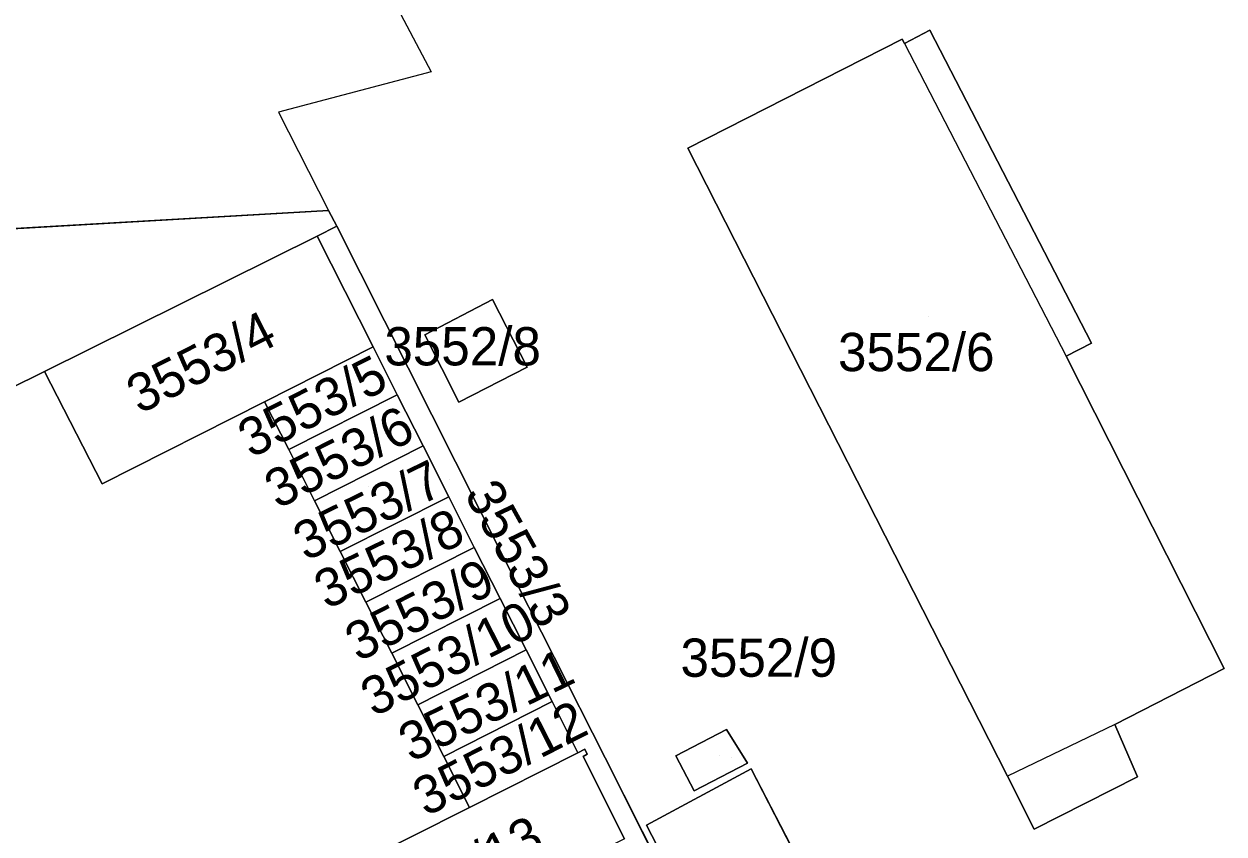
# Model space of a CAD drawing. Extents: x -262657 to -261595, y -1238015 to -1237156.
# Drawn here: x -262494.6 to -262431.9, y -1237435.4 to -1237393.1 of the extents above; entities that cross this region are included whole.
import ezdxf

# ---------------------------------------------------------------- set-up
doc = ezdxf.new("R2010")
doc.units = 0
for name, color, linetype in [('body_kn', 7, 'Continuous'), ('kladpar_druhypozemkov', 7, 'Continuous'), ('kladpar_hranice', 7, 'Continuous'), ('kladpar_parcelnecisla', 7, 'Continuous'), ('kladpar_plochy', 7, 'Continuous'), ('kladpar_sipky', 7, 'Continuous'), ('zappar_hrandruhpozemk', 7, 'Continuous')]:
    doc.layers.add(name, color=color, linetype=linetype)

msp = doc.modelspace()

# ---------------------------------------------------------------- linework, layer by layer
at = {"layer": 'body_kn'}
for p, q in [((-262448.76, -1237393.9), (-262448.76, -1237393.9)), ((-262447.31, -1237393.44), (-262447.31, -1237393.44)), ((-262448.64, -1237394.13), (-262448.64, -1237394.13)), ((-262448.64, -1237394.13), (-262448.64, -1237394.13)), ((-262473.37, -1237395.61), (-262473.37, -1237395.61)), ((-262481.34, -1237397.71), (-262481.34, -1237397.71)), ((-262459.95, -1237399.59), (-262459.95, -1237399.59)), ((-262459.95, -1237399.59), (-262459.95, -1237399.59)), ((-262478.73, -1237402.85), (-262478.73, -1237402.85)), ((-262478.29, -1237403.67), (-262478.29, -1237403.67)), ((-262478.29, -1237403.67), (-262478.29, -1237403.67)), ((-262479.33, -1237404.19), (-262479.33, -1237404.19)), ((-262479.33, -1237404.19), (-262479.33, -1237404.19)), ((-262470.16, -1237407.5), (-262470.16, -1237407.5)), ((-262470.16, -1237407.5), (-262470.16, -1237407.5)), ((-262473.69, -1237409.35), (-262473.69, -1237409.35)), ((-262476.4, -1237409.98), (-262476.4, -1237409.98)), ((-262476.4, -1237409.98), (-262476.4, -1237409.98)), ((-262438.86, -1237409.78), (-262438.86, -1237409.78)), ((-262440.19, -1237410.47), (-262440.19, -1237410.47)), ((-262493.57, -1237411.26), (-262493.57, -1237411.26)), ((-262468.36, -1237411.05), (-262468.36, -1237411.05)), ((-262475.14, -1237412.48), (-262475.14, -1237412.48)), ((-262475.14, -1237412.48), (-262475.14, -1237412.48)), ((-262482.07, -1237412.85), (-262482.07, -1237412.85)), ((-262471.92, -1237412.87), (-262471.92, -1237412.87)), ((-262473.79, -1237415.15), (-262473.79, -1237415.15)), ((-262473.79, -1237415.15), (-262473.79, -1237415.15)), ((-262480.81, -1237415.34), (-262480.81, -1237415.34)), ((-262490.55, -1237417.14), (-262490.55, -1237417.14)), ((-262479.46, -1237418.02), (-262479.46, -1237418.02)), ((-262472.45, -1237417.81), (-262472.45, -1237417.81)), ((-262472.45, -1237417.81), (-262472.45, -1237417.81)), ((-262478.12, -1237420.68), (-262478.12, -1237420.68)), ((-262471.12, -1237420.46), (-262471.12, -1237420.46)), ((-262471.12, -1237420.46), (-262471.12, -1237420.46)), ((-262469.6, -1237420.93), (-262469.6, -1237420.93)), ((-262476.78, -1237423.32), (-262476.78, -1237423.32)), ((-262469.77, -1237423.13), (-262469.77, -1237423.13)), ((-262469.77, -1237423.13), (-262469.77, -1237423.13)), ((-262468.41, -1237425.82), (-262468.41, -1237425.82)), ((-262468.41, -1237425.82), (-262468.41, -1237425.82)), ((-262475.43, -1237425.99), (-262475.43, -1237425.99)), ((-262431.94, -1237426.78), (-262431.94, -1237426.78)), ((-262474.07, -1237428.68), (-262474.07, -1237428.68)), ((-262467.05, -1237428.52), (-262467.05, -1237428.52)), ((-262467.05, -1237428.52), (-262467.05, -1237428.52)), ((-262457.94, -1237429.98), (-262457.94, -1237429.98)), ((-262437.65, -1237429.72), (-262437.65, -1237429.72)), ((-262437.65, -1237429.72), (-262437.65, -1237429.72)), ((-262472.71, -1237431.38), (-262472.71, -1237431.38)), ((-262465.7, -1237431.19), (-262465.7, -1237431.19)), ((-262465.7, -1237431.19), (-262465.7, -1237431.19)), ((-262465.43, -1237431.39), (-262465.43, -1237431.39)), ((-262465.34, -1237431.01), (-262465.34, -1237431.01)), ((-262465.21, -1237431.27), (-262465.21, -1237431.27)), ((-262464.28, -1237431.46), (-262464.28, -1237431.46)), ((-262460.58, -1237431.35), (-262460.58, -1237431.35)), ((-262460.58, -1237431.35), (-262460.58, -1237431.35)), ((-262456.84, -1237431.73), (-262456.84, -1237431.73)), ((-262456.65, -1237432.03), (-262456.65, -1237432.03)), ((-262443.26, -1237432.42), (-262443.26, -1237432.42)), ((-262436.46, -1237432.44), (-262436.46, -1237432.44)), ((-262459.63, -1237433.18), (-262459.63, -1237433.18)), ((-262471.37, -1237434.05), (-262471.37, -1237434.05)), ((-262462.11, -1237434.98), (-262462.11, -1237434.98)), ((-262462.11, -1237434.98), (-262462.11, -1237434.98)), ((-262441.86, -1237435.18), (-262441.86, -1237435.18))]:
    msp.add_line(p, q, dxfattribs=at)
at = {"layer": 'kladpar_druhypozemkov'}
for p, q in [((-262447.37, -1237408.4), (-262447.37, -1237408.4)), ((-262484.67, -1237409.31), (-262484.67, -1237409.31)), ((-262470.61, -1237409.19), (-262470.61, -1237409.19)), ((-262479.21, -1237411.98), (-262479.21, -1237411.98)), ((-262477.97, -1237414.73), (-262477.97, -1237414.73)), ((-262472.42, -1237416.89), (-262472.42, -1237416.89)), ((-262476.65, -1237417.29), (-262476.65, -1237417.29)), ((-262475.37, -1237420.02), (-262475.37, -1237420.02)), ((-262474.18, -1237422.69), (-262474.18, -1237422.69)), ((-262472.66, -1237425.55), (-262472.66, -1237425.55)), ((-262471.32, -1237427.85), (-262471.32, -1237427.85)), ((-262469.89, -1237430.69), (-262469.89, -1237430.69)), ((-262458.31, -1237431.31), (-262458.31, -1237431.31))]:
    msp.add_line(p, q, dxfattribs=at)
at = {"layer": 'kladpar_hranice'}
for points in [[(-262437.9, -1237483.33), (-262449.72, -1237460.31), (-262464.28, -1237431.46), (-262469.6, -1237420.93), (-262478.29, -1237403.67), (-262478.73, -1237402.85), (-262506.09, -1237404.44), (-262514.95, -1237386.75), (-262519.84, -1237377.16), (-262513.51, -1237373.66), (-262507.3, -1237370.26), (-262500.71, -1237366.65), (-262500.15, -1237367.7), (-262490.13, -1237386.72), (-262486.03, -1237384.56), (-262484.61, -1237387.26), (-262481.8, -1237385.78), (-262483.22, -1237383.08), (-262479.4, -1237381.2)], [(-262478.29, -1237403.67), (-262479.33, -1237404.19), (-262493.57, -1237411.26), (-262501.01, -1237414.95), (-262518.77, -1237390.55), (-262514.95, -1237386.75), (-262506.09, -1237404.44), (-262478.73, -1237402.85), (-262478.29, -1237403.67)], [(-262459.95, -1237399.59), (-262448.76, -1237393.9), (-262448.64, -1237394.13), (-262447.31, -1237393.44), (-262438.86, -1237409.78), (-262440.19, -1237410.47), (-262431.94, -1237426.78), (-262437.65, -1237429.72), (-262436.46, -1237432.44), (-262441.86, -1237435.18), (-262443.26, -1237432.42), (-262459.95, -1237399.59)], [(-262448.76, -1237393.9), (-262459.95, -1237399.59), (-262443.26, -1237432.42), (-262441.86, -1237435.18), (-262436.46, -1237432.44), (-262437.65, -1237429.72), (-262431.94, -1237426.78), (-262440.19, -1237410.47), (-262438.86, -1237409.78), (-262447.31, -1237393.44), (-262448.64, -1237394.13), (-262448.76, -1237393.9)], [(-262463.26, -1237435.69), (-262465.43, -1237431.39), (-262465.21, -1237431.27), (-262465.34, -1237431.01), (-262465.7, -1237431.19), (-262467.05, -1237428.52), (-262468.41, -1237425.82), (-262469.77, -1237423.13), (-262471.12, -1237420.46), (-262472.45, -1237417.81), (-262473.79, -1237415.15), (-262475.14, -1237412.48), (-262476.4, -1237409.98), (-262479.33, -1237404.19), (-262478.29, -1237403.67)], [(-262478.29, -1237403.67), (-262469.6, -1237420.93), (-262464.28, -1237431.46), (-262449.72, -1237460.31)], [(-262479.33, -1237404.19), (-262476.4, -1237409.98), (-262482.07, -1237412.85), (-262490.55, -1237417.14), (-262493.57, -1237411.26), (-262479.33, -1237404.19)], [(-262470.16, -1237407.5), (-262468.36, -1237411.05), (-262471.92, -1237412.87), (-262473.69, -1237409.35), (-262470.16, -1237407.5)], [(-262468.36, -1237411.05), (-262470.16, -1237407.5), (-262473.69, -1237409.35), (-262471.92, -1237412.87), (-262468.36, -1237411.05)], [(-262476.4, -1237409.98), (-262475.14, -1237412.48), (-262480.81, -1237415.34), (-262482.07, -1237412.85), (-262476.4, -1237409.98)], [(-262501.01, -1237414.95), (-262493.57, -1237411.26), (-262490.55, -1237417.14), (-262482.07, -1237412.85), (-262480.81, -1237415.34), (-262479.46, -1237418.02), (-262478.12, -1237420.68), (-262476.78, -1237423.32), (-262475.43, -1237425.99), (-262474.07, -1237428.68), (-262472.71, -1237431.38), (-262471.37, -1237434.05), (-262480.58, -1237438.69), (-262480.44, -1237438.97), (-262480.06, -1237438.78), (-262477.9, -1237443.08), (-262475.74, -1237447.37), (-262473.58, -1237451.67), (-262471.42, -1237455.97), (-262469.26, -1237460.27), (-262467.1, -1237464.57), (-262467.48, -1237464.76), (-262467.34, -1237465.04), (-262464.28, -1237463.5)], [(-262475.14, -1237412.48), (-262473.79, -1237415.15), (-262479.46, -1237418.02), (-262480.81, -1237415.34), (-262475.14, -1237412.48)], [(-262473.79, -1237415.15), (-262472.45, -1237417.81), (-262478.12, -1237420.68), (-262479.46, -1237418.02), (-262473.79, -1237415.15)], [(-262472.45, -1237417.81), (-262471.12, -1237420.46), (-262476.78, -1237423.32), (-262478.12, -1237420.68), (-262472.45, -1237417.81)], [(-262471.12, -1237420.46), (-262469.77, -1237423.13), (-262475.43, -1237425.99), (-262476.78, -1237423.32), (-262471.12, -1237420.46)], [(-262469.77, -1237423.13), (-262468.41, -1237425.82), (-262474.07, -1237428.68), (-262475.43, -1237425.99), (-262469.77, -1237423.13)], [(-262468.41, -1237425.82), (-262467.05, -1237428.52), (-262472.71, -1237431.38), (-262474.07, -1237428.68), (-262468.41, -1237425.82)], [(-262467.05, -1237428.52), (-262465.7, -1237431.19), (-262471.37, -1237434.05), (-262472.71, -1237431.38), (-262467.05, -1237428.52)], [(-262460.58, -1237431.35), (-262457.94, -1237429.98), (-262456.84, -1237431.73), (-262459.63, -1237433.18), (-262460.58, -1237431.35)], [(-262457.94, -1237429.98), (-262460.58, -1237431.35), (-262459.63, -1237433.18), (-262456.84, -1237431.73), (-262457.94, -1237429.98)], [(-262465.7, -1237431.19), (-262465.34, -1237431.01), (-262465.21, -1237431.27), (-262465.43, -1237431.39), (-262463.26, -1237435.69), (-262477.9, -1237443.08), (-262480.06, -1237438.78), (-262480.44, -1237438.97), (-262480.58, -1237438.69), (-262471.37, -1237434.05), (-262465.7, -1237431.19)], [(-262462.11, -1237434.98), (-262456.65, -1237432.03), (-262433.8, -1237476.18), (-262439.24, -1237479.29), (-262462.11, -1237434.98)], [(-262456.65, -1237432.03), (-262462.11, -1237434.98), (-262439.24, -1237479.29), (-262433.8, -1237476.18), (-262456.65, -1237432.03)]]:
    msp.add_lwpolyline(points, dxfattribs=at)
at = {"layer": 'kladpar_plochy'}
for p, q in [((-262448.76, -1237393.9), (-262459.95, -1237399.59)), ((-262448.64, -1237394.13), (-262448.76, -1237393.9)), ((-262447.31, -1237393.44), (-262448.64, -1237394.13)), ((-262438.86, -1237409.78), (-262447.31, -1237393.44)), ((-262459.95, -1237399.59), (-262443.26, -1237432.42)), ((-262478.73, -1237402.85), (-262506.09, -1237404.44)), ((-262478.29, -1237403.67), (-262478.73, -1237402.85)), ((-262469.6, -1237420.93), (-262478.29, -1237403.67)), ((-262470.16, -1237407.5), (-262473.69, -1237409.35)), ((-262468.36, -1237411.05), (-262470.16, -1237407.5)), ((-262473.69, -1237409.35), (-262471.92, -1237412.87)), ((-262440.19, -1237410.47), (-262438.86, -1237409.78)), ((-262431.94, -1237426.78), (-262440.19, -1237410.47)), ((-262471.92, -1237412.87), (-262468.36, -1237411.05)), ((-262464.28, -1237431.46), (-262469.6, -1237420.93)), ((-262437.65, -1237429.72), (-262431.94, -1237426.78)), ((-262457.94, -1237429.98), (-262460.58, -1237431.35)), ((-262456.84, -1237431.73), (-262457.94, -1237429.98)), ((-262436.46, -1237432.44), (-262437.65, -1237429.72)), ((-262449.72, -1237460.31), (-262464.28, -1237431.46)), ((-262460.58, -1237431.35), (-262459.63, -1237433.18)), ((-262456.65, -1237432.03), (-262462.11, -1237434.98)), ((-262459.63, -1237433.18), (-262456.84, -1237431.73)), ((-262433.8, -1237476.18), (-262456.65, -1237432.03)), ((-262443.26, -1237432.42), (-262441.86, -1237435.18)), ((-262441.86, -1237435.18), (-262436.46, -1237432.44)), ((-262462.11, -1237434.98), (-262439.24, -1237479.29))]:
    msp.add_line(p, q, dxfattribs=at)
for points in [[(-262478.29, -1237403.67), (-262479.33, -1237404.19), (-262493.57, -1237411.26), (-262501.01, -1237414.95), (-262518.77, -1237390.55), (-262514.95, -1237386.75), (-262506.09, -1237404.44), (-262478.73, -1237402.85)], [(-262459.95, -1237399.59), (-262448.76, -1237393.9), (-262448.64, -1237394.13), (-262447.31, -1237393.44), (-262438.86, -1237409.78), (-262440.19, -1237410.47), (-262431.94, -1237426.78), (-262437.65, -1237429.72), (-262436.46, -1237432.44), (-262441.86, -1237435.18), (-262443.26, -1237432.42)], [(-262479.33, -1237404.19), (-262476.4, -1237409.98), (-262482.07, -1237412.85), (-262490.55, -1237417.14), (-262493.57, -1237411.26)], [(-262470.16, -1237407.5), (-262468.36, -1237411.05), (-262471.92, -1237412.87), (-262473.69, -1237409.35)], [(-262476.4, -1237409.98), (-262475.14, -1237412.48), (-262480.81, -1237415.34), (-262482.07, -1237412.85)], [(-262475.14, -1237412.48), (-262473.79, -1237415.15), (-262479.46, -1237418.02), (-262480.81, -1237415.34)], [(-262473.79, -1237415.15), (-262472.45, -1237417.81), (-262478.12, -1237420.68), (-262479.46, -1237418.02)], [(-262472.45, -1237417.81), (-262471.12, -1237420.46), (-262476.78, -1237423.32), (-262478.12, -1237420.68)], [(-262471.12, -1237420.46), (-262469.77, -1237423.13), (-262475.43, -1237425.99), (-262476.78, -1237423.32)], [(-262469.77, -1237423.13), (-262468.41, -1237425.82), (-262474.07, -1237428.68), (-262475.43, -1237425.99)], [(-262468.41, -1237425.82), (-262467.05, -1237428.52), (-262472.71, -1237431.38), (-262474.07, -1237428.68)], [(-262467.05, -1237428.52), (-262465.7, -1237431.19), (-262471.37, -1237434.05), (-262472.71, -1237431.38)], [(-262460.58, -1237431.35), (-262457.94, -1237429.98), (-262456.84, -1237431.73), (-262459.63, -1237433.18)], [(-262465.7, -1237431.19), (-262465.34, -1237431.01), (-262465.21, -1237431.27), (-262465.43, -1237431.39), (-262463.26, -1237435.69), (-262477.9, -1237443.08), (-262480.06, -1237438.78), (-262480.44, -1237438.97), (-262480.58, -1237438.69), (-262471.37, -1237434.05)], [(-262462.11, -1237434.98), (-262456.65, -1237432.03), (-262433.8, -1237476.18), (-262439.24, -1237479.29)]]:
    msp.add_lwpolyline(points, close=True, dxfattribs=at)
for points in [[(-262463.26, -1237435.69), (-262465.43, -1237431.39), (-262465.21, -1237431.27), (-262465.34, -1237431.01), (-262465.7, -1237431.19), (-262467.05, -1237428.52), (-262468.41, -1237425.82), (-262469.77, -1237423.13), (-262471.12, -1237420.46), (-262472.45, -1237417.81), (-262473.79, -1237415.15), (-262475.14, -1237412.48), (-262476.4, -1237409.98), (-262479.33, -1237404.19), (-262478.29, -1237403.67), (-262469.6, -1237420.93), (-262464.28, -1237431.46), (-262449.72, -1237460.31)], [(-262501.01, -1237414.95), (-262493.57, -1237411.26), (-262490.55, -1237417.14), (-262482.07, -1237412.85), (-262480.81, -1237415.34), (-262479.46, -1237418.02), (-262478.12, -1237420.68), (-262476.78, -1237423.32), (-262475.43, -1237425.99), (-262474.07, -1237428.68), (-262472.71, -1237431.38), (-262471.37, -1237434.05), (-262480.58, -1237438.69)]]:
    msp.add_lwpolyline(points, dxfattribs=at)
at = {"layer": 'kladpar_sipky'}
msp.add_line((-262457.7, -1237431.42), (-262457.7, -1237431.42), dxfattribs=at)
at = {"layer": 'zappar_hrandruhpozemk'}
for p, q in [((-262477.83, -1237387.12), (-262473.37, -1237395.61)), ((-262448.64, -1237394.13), (-262440.19, -1237410.47)), ((-262473.37, -1237395.61), (-262481.34, -1237397.71)), ((-262481.34, -1237397.71), (-262478.73, -1237402.85)), ((-262437.65, -1237429.72), (-262443.26, -1237432.42))]:
    msp.add_line(p, q, dxfattribs=at)

# ---------------------------------------------------------------- texts
at = {"layer": 'kladpar_parcelnecisla'}
for s, rotation, p in [('3553/4', 27, (-262488.598, -1237413.516)), ('3553/5', 27, (-262482.777, -1237415.821)), ('3553/6', 27, (-262481.388, -1237418.476)), ('3553/7', 26, (-262479.921, -1237421.202)), ('3553/3', 299, (-262471.668, -1237417.668)), ('3553/8', 26, (-262478.825, -1237423.723)), ('3553/9', 27, (-262477.178, -1237426.466)), ('3553/10', 27, (-262476.364, -1237429.342)), ('3553/11', 26, (-262474.417, -1237431.71)), ('3553/12', 27, (-262473.643, -1237434.548)), ('3553/13', 27, (-262475.947, -1237440.565))]:
    msp.add_text(s, height=2, rotation=rotation, dxfattribs=at).set_placement(p)
for s, p in [('3552/8', (-262475.813, -1237410.95)), ('3552/6', (-262452.109, -1237411.25)), ('3552/9', (-262460.339, -1237427.22))]:
    msp.add_text(s, height=2, dxfattribs=at).set_placement(p)

doc.saveas('drawing.dxf')
